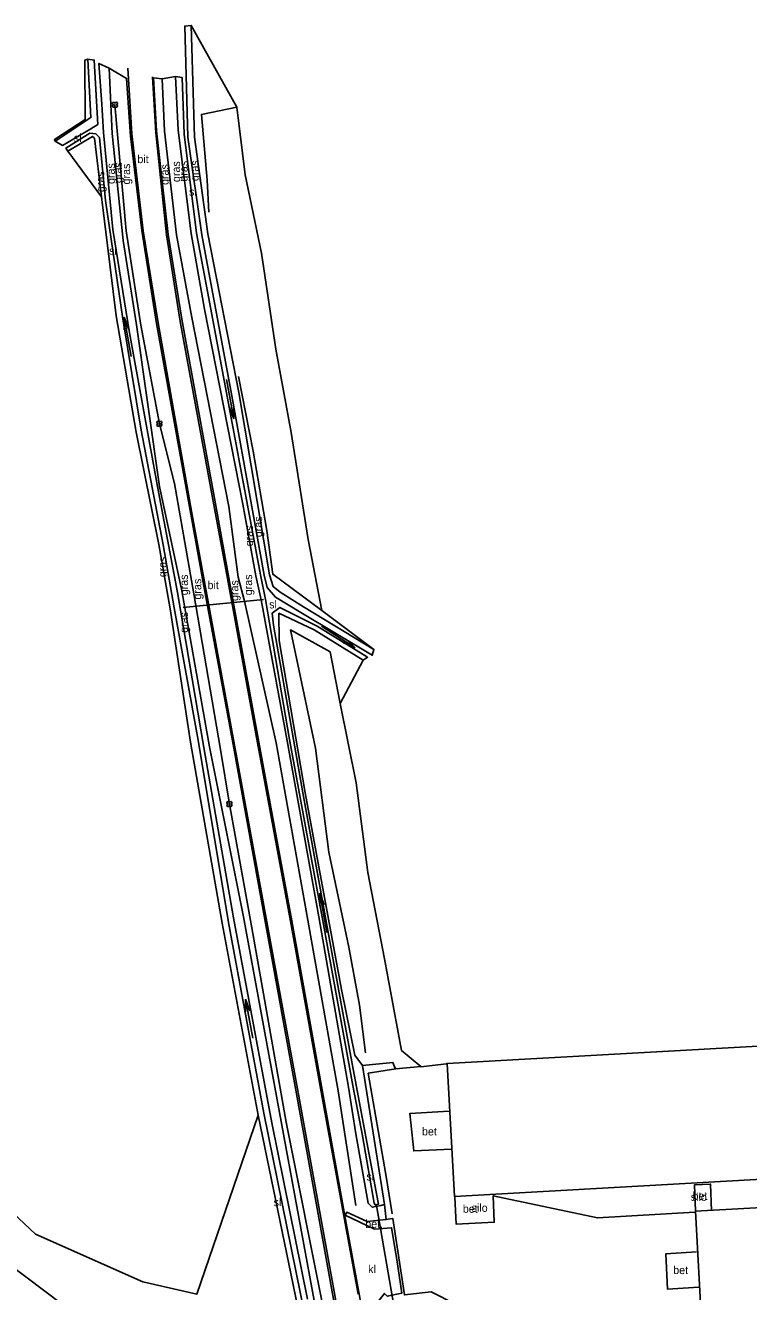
# Model space of a CAD drawing. Extents: x 154825 to 158680, y 370717 to 378075.
# Drawn here: x 155424.8 to 155515.3, y 377327.8 to 377486.1 of the extents above; entities that cross this region are included whole.
import ezdxf

# ---------------------------------------------------------------- set-up
doc = ezdxf.new("R2010")
doc.units = 0
for name, color, linetype in [('beton', 7, 'Continuous'), ('bitumenverharding(vs)', 7, 'Continuous'), ('boom', 7, 'Continuous'), ('breuklijn', 7, 'Continuous'), ('cultuurscheiding', 7, 'Continuous'), ('deelstreep(1-3)', 7, 'Continuous'), ('duiker lijn', 7, 'Continuous'), ('gebouw algemeen', 7, 'Continuous'), ('grazige vegetatie(vs)', 7, 'Continuous'), ('haag geschoren', 7, 'Continuous'), ('haag geschoren+insteek', 7, 'Continuous'), ('hoogteverschillijn', 7, 'Continuous'), ('insteek sloot', 7, 'Continuous'), ('klinkerverharding(vs)', 7, 'Continuous'), ('maaiveldlijn algemeen - gesloten verharding', 7, 'Continuous'), ('maaiveldlijn algemeen - open verharding', 7, 'Continuous'), ('maaiveldlijn algemeen - verharding algemeen', 7, 'Continuous'), ('raster - hek', 7, 'Continuous'), ('Silo_cel', 7, 'Continuous'), ('Sloot bodem', 7, 'Continuous'), ('sloot(vs)', 7, 'Continuous'), ('stroomrichting  watergangen', 7, 'Continuous'), ('vlak_akkerland', 7, 'Continuous'), ('vlak_Grasland', 7, 'Continuous'), ('vlak_Grazige_vegetatie', 7, 'Continuous')]:
    doc.layers.add(name, color=color, linetype=linetype)

msp = doc.modelspace()

# ---------------------------------------------------------------- linework, layer by layer
at = {"layer": 'boom'}
msp.add_lwpolyline([(155450.36, 377388.74), (155453.14, 377373.27), (155457.45, 377348.99), (155462.1, 377325.61)], dxfattribs=at)
for centre in [(155436.04, 377476.14), (155441.6, 377436.27), (155450.36, 377388.74)]:
    msp.add_circle(centre, 0.006, dxfattribs=at)
for centre, start, end in [((155435.89, 377476.3), 357.075, 272.925), ((155435.89, 377475.98), 87.075, 2.925), ((155436.2, 377476.3), 267.075, 182.925), ((155436.2, 377475.98), 177.075, 92.925), ((155441.45, 377436.43), 357.075, 272.925), ((155441.45, 377436.11), 87.075, 2.925), ((155441.76, 377436.43), 267.075, 182.925), ((155441.76, 377436.11), 177.075, 92.925), ((155450.2, 377388.89), 357.075, 272.925), ((155450.2, 377388.58), 87.075, 2.925), ((155450.52, 377388.89), 267.075, 182.925), ((155450.52, 377388.58), 177.075, 92.925)]:
    msp.add_arc(centre, 0.158, start, end, dxfattribs=at)
at = {"layer": 'breuklijn'}
for points in [[(155441.93, 377479.4), (155442.22, 377472.86), (155443.76, 377459.87), (155445.64, 377449.54), (155450.27, 377425.94), (155451.44, 377417.08), (155452.22, 377414.08), (155456.2, 377396.39), (155460.14, 377374.23), (155463.95, 377352.91), (155466.15, 377338.57)], [(155441.6, 377436.27), (155443.47, 377428.79), (155445.9, 377415.02), (155449.24, 377395.55), (155450.36, 377388.74)]]:
    msp.add_lwpolyline(points, dxfattribs=at)
at = {"layer": 'cultuurscheiding'}
msp.add_lwpolyline([(155470.99, 377355.91), (155471.15, 377355.63)], dxfattribs=at)
at = {"layer": 'deelstreep(1-3)'}
for points in [[(155437.66, 377480.71), (155438.16, 377472.53), (155439.59, 377460.39), (155441.45, 377448.89), (155445.6, 377425.35), (155447.26, 377416.5), (155450.91, 377396.55), (155455.12, 377373.55), (155458.93, 377352.67), (155463.84, 377325.72), (155466.95, 377308.73), (155469.14, 377296.77), (155472.64, 377277.72), (155474.84, 377265.78), (155475.54, 377261.77), (155476.99, 377253.79), (155477.67, 377248.89), (155478.31, 377241.77), (155478.57, 377236.78), (155478.71, 377229.69), (155478.45, 377221.57), (155477.91, 377213.49), (155477.46, 377208.51), (155476.34, 377200.59)], [(155440.75, 377479.62), (155441.17, 377472.64), (155442.51, 377459.88), (155444.19, 377449.04), (155448.51, 377425.69), (155450.11, 377416.95), (155453.67, 377397.53), (155457.97, 377374.09), (155462.05, 377351.58), (155466.44, 377327.46)]]:
    msp.add_lwpolyline(points, dxfattribs=at)
at = {"layer": 'duiker lijn'}
for points in [[(155454.6, 377414.3), (155444.57, 377413.3)], [(155471.29, 377323.9), (155468.74, 377338.58)]]:
    msp.add_lwpolyline(points, dxfattribs=at)
at = {"layer": 'gebouw algemeen'}
for points in [[(155477.56, 377356.3), (155541.13, 377359.87), (155542.07, 377343.27)], [(155477.56, 377356.3), (155478.49, 377339.7), (155542.07, 377343.27)], [(155509.43, 377323.28), (155551.72, 377325.63), (155550.88, 377340.19), (155508.61, 377337.85)], [(155508.61, 377337.85), (155509.43, 377323.28)]]:
    msp.add_lwpolyline(points, dxfattribs=at)
at = {"layer": 'haag geschoren'}
for points in [[(155466.98, 377356.05), (155470.79, 377356.45), (155470.99, 377355.91)], [(155469.73, 377338.7), (155469.93, 377336.83)]]:
    msp.add_lwpolyline(points, dxfattribs=at)
at = {"layer": 'haag geschoren+insteek'}
msp.add_lwpolyline([(155469.73, 377338.7), (155466.98, 377356.05)], dxfattribs=at)
at = {"layer": 'hoogteverschillijn'}
for points in [[(155451.47, 377442.16), (155453.33, 377432.86), (155455.05, 377422.95), (155455.77, 377417.47), (155461.92, 377412.95), (155460.22, 377421.82), (155458.09, 377435.16), (155456.15, 377445.58), (155454.35, 377457.58), (155452.31, 377467.38), (155451.3, 377475.83), (155446.87, 377474.93), (155447.57, 377466.71), (155447.77, 377462.71)], [(155471.85, 377357.93), (155469.73, 377369.39), (155467.64, 377380.18), (155466.19, 377391.38), (155464.22, 377401.31), (155462.93, 377407.78), (155458.01, 377410.51), (155461.13, 377395.73), (155462.78, 377382.72), (155465.28, 377370.84), (155466.6, 377363.59), (155467.35, 377357.66)], [(155417.64, 377342.88), (155426.1, 377334.99), (155439.54, 377329.02), (155446.29, 377327.48)], [(155431.86, 377324.38), (155422.53, 377331.44)]]:
    msp.add_lwpolyline(points, dxfattribs=at)
at = {"layer": 'insteek sloot'}
for points in [[(155468.42, 377408.07), (155459.63, 377413.37), (155456.7, 377415.23), (155455.84, 377415.91), (155455.37, 377417.37), (155451.54, 377440.16), (155447.67, 377460), (155446.01, 377472.1), (155445.59, 377486.07)], [(155432.66, 377481.84), (155433.05, 377474.55), (155428.56, 377471.58)], [(155435.31, 377480.71), (155435.7, 377472.57), (155437.06, 377459.16), (155438.75, 377448.64), (155441.6, 377428.42), (155444.41, 377415.39), (155447.88, 377395.89), (155452.11, 377374.66), (155456.6, 377350.19), (155460.96, 377326.69), (155463.34, 377313.74), (155464.93, 377304.29), (155464.68, 377303.32), (155463.8, 377303.1), (155463.38, 377303.31)], [(155443.62, 377479.66), (155443.95, 377472.96), (155445.59, 377460.04), (155447.26, 377450.59), (155452.03, 377426.21), (155453.64, 377417.26), (155454.33, 377414.28), (155457.58, 377396.65), (155461.52, 377374.64), (155465.23, 377353.37), (155466.16, 377347.52), (155467.68, 377338.84), (155468.2, 377338.35), (155469.29, 377338.58), (155469.73, 377338.7)], [(155430.15, 377470.36), (155433.22, 377472.19), (155433.5, 377471.96), (155434.37, 377464.65), (155436.19, 377449.77), (155438.71, 377435.24), (155441.52, 377421.18), (155442.96, 377413.12), (155445.51, 377396.47), (155449.46, 377373.84), (155453.96, 377349.87), (155459.15, 377324.59), (155463.38, 377303.31)], [(155466.98, 377356.05), (155466.02, 377357.34), (155464.37, 377365.55), (155459.82, 377390.12), (155456.56, 377409.2), (155456.55, 377412.58), (155460.97, 377410.52), (155467.06, 377406.74)]]:
    msp.add_lwpolyline(points, dxfattribs=at)
at = {"layer": 'maaiveldlijn algemeen - gesloten verharding'}
for points in [[(155437.51, 377479.44), (155437.98, 377472.22), (155439.4, 377460.42), (155441.26, 377448.82), (155445.52, 377424.98), (155447.08, 377416.43), (155450.73, 377396.66), (155454.95, 377373.38), (155458.76, 377352.51), (155463.59, 377325.7)], [(155440.87, 377479.51), (155441.25, 377472.89), (155442.7, 377459.94), (155444.41, 377449.33), (155448.69, 377425.79), (155450.3, 377417), (155454.05, 377396.46), (155458.15, 377374.14), (155462.15, 377351.83), (155464.8, 377337.25), (155467.15, 377324.3)], [(155436.04, 377476.14), (155437.44, 377460.38), (155439.3, 377448.6), (155441.6, 377436.27)]]:
    msp.add_lwpolyline(points, dxfattribs=at)
at = {"layer": 'maaiveldlijn algemeen - open verharding'}
msp.add_lwpolyline([(155467.15, 377324.3), (155469.73, 377327.57), (155470.08, 377327.22), (155471.89, 377327.59), (155471.28, 377331.8), (155470.62, 377335.78), (155468.5, 377335.59), (155464.84, 377337.34)], dxfattribs=at)
at = {"layer": 'maaiveldlijn algemeen - verharding algemeen'}
for points in [[(155470.72, 377337.52), (155469.92, 377342.43), (155467.72, 377355.09), (155471.15, 377355.63)], [(155471.15, 377355.63), (155474.27, 377355.93), (155474.29, 377355.89), (155477.51, 377356.26), (155477.56, 377356.3)], [(155477.83, 377350.35), (155472.9, 377350.04), (155473.39, 377345.38), (155478.11, 377345.62)], [(155508.61, 377337.85), (155508.5, 377341.16), (155510.5, 377341.23), (155510.61, 377337.91)], [(155478.52, 377339.6), (155478.69, 377336.23), (155483.47, 377336.47), (155483.33, 377339.77), (155496.36, 377337.01), (155508.53, 377337.71)], [(155464.8, 377337.25), (155465.03, 377337.72), (155467.58, 377336.54), (155469.93, 377336.83)], [(155469.93, 377336.83), (155470.43, 377336.89), (155470.78, 377336.95), (155472.24, 377327.39), (155475.56, 377327.76), (155481.58, 377324.71), (155486.52, 377322.24)], [(155509.05, 377328.35), (155505.13, 377328.1), (155504.92, 377332.53), (155508.75, 377332.78)]]:
    msp.add_lwpolyline(points, dxfattribs=at)
at = {"layer": 'raster - hek'}
msp.add_lwpolyline([(155432.26, 377481.7), (155432.31, 377474.29), (155428.48, 377471.8)], dxfattribs=at)
at = {"layer": 'Sloot bodem'}
for points in [[(155468.2, 377407.34), (155459.27, 377412.67), (155456.12, 377414.6), (155455.06, 377415.79), (155454.7, 377417.36), (155450.64, 377439.77), (155446.89, 377459.87), (155445.16, 377472.08), (155444.78, 377485.97)], [(155429.47, 377471.06), (155433.05, 377473.13), (155433.91, 377473.69), (155433.46, 377481.73)], [(155434.04, 377481.32), (155434.42, 377476.2), (155434.62, 377472.69), (155435.8, 377460.55), (155437.85, 377447.62), (155441.35, 377428.42), (155443.88, 377415.17), (155447.17, 377395.8), (155450.88, 377374.51), (155455.65, 377348.89), (155460.12, 377326.87)], [(155444.43, 377479.54), (155444.68, 377472.47), (155446.22, 377460.09), (155448.02, 377450.6), (155452.6, 377426.09), (155454.24, 377417.39), (155454.85, 377414.29), (155457.86, 377396.79), (155461.94, 377374.6), (155465.78, 377353.55), (155466.98, 377347.26), (155468.44, 377338.87), (155468.59, 377338.64), (155468.99, 377338.72), (155468.91, 377339.16), (155465.73, 377356.04), (155463.99, 377365.61), (155459.54, 377390.16), (155455.85, 377411.08), (155455.71, 377412.6), (155456.64, 377413.31), (155461.31, 377410.98), (155467.63, 377407.09)], [(155459.81, 377324.63), (155454.65, 377350.1), (155450.22, 377373.93), (155446.45, 377396.74), (155443.46, 377413.28), (155442.06, 377421.12), (155439.34, 377435.49), (155437.04, 377449.4), (155434.86, 377464.18), (155434.13, 377472.05), (155433.66, 377472.52), (155432.9, 377472.61), (155429.92, 377470.73)]]:
    msp.add_lwpolyline(points, dxfattribs=at)
at = {"layer": 'stroomrichting  watergangen'}
for p, q in [((155437.18, 377449.59), (155437.19, 377448.01)), ((155438.09, 377444.69), (155437.19, 377449.6)), ((155437.19, 377449.6), (155437.74, 377448.12)), ((155450, 377441.81), (155450.89, 377436.9)), ((155450.89, 377436.9), (155450.34, 377438.38)), ((155450.9, 377436.91), (155450.9, 377438.49)), ((155461.87, 377410.98), (155466.06, 377408.27)), ((155466.05, 377408.29), (155464.9, 377409.37)), ((155466.06, 377408.27), (155464.6, 377408.88)), ((155461.64, 377377.58), (155461.64, 377376)), ((155462.54, 377372.69), (155461.65, 377377.6)), ((155461.65, 377377.6), (155462.19, 377376.12)), ((155452.36, 377364.36), (155452.37, 377362.78)), ((155453.27, 377359.46), (155452.38, 377364.37)), ((155452.38, 377364.37), (155452.92, 377362.89))]:
    msp.add_line(p, q, dxfattribs=at)
at = {"layer": 'vlak_akkerland'}
msp.add_lwpolyline([(155332.6, 377406.06), (155336.93, 377409.48), (155343.4, 377413.36), (155347.88, 377416.5), (155347.67, 377415.7), (155352.79, 377409.99), (155356.85, 377405.55), (155360.64, 377401.81), (155369.42, 377391.91), (155377.47, 377383.61), (155385.94, 377374.1), (155392.86, 377367.05), (155401.97, 377357.18), (155410.79, 377349.42), (155417.64, 377342.88), (155426.1, 377334.99), (155439.54, 377329.02), (155446.29, 377327.48), (155453.96, 377349.87), (155459.15, 377324.59)], dxfattribs=at)
at = {"layer": 'vlak_Grasland'}
for points in [[(155461.92, 377412.95), (155468.42, 377408.07), (155459.63, 377413.37), (155456.7, 377415.23), (155455.84, 377415.91), (155455.37, 377417.37), (155451.54, 377440.16), (155447.67, 377460), (155446.01, 377472.1), (155445.59, 377486.07), (155451.3, 377475.83), (155452.31, 377467.38), (155454.35, 377457.58), (155456.15, 377445.58), (155458.09, 377435.16), (155460.22, 377421.82)], [(155471.85, 377357.93), (155474.27, 377355.93), (155471.15, 377355.63), (155470.99, 377355.91), (155470.79, 377356.45), (155466.98, 377356.05), (155466.02, 377357.34), (155464.37, 377365.55), (155459.82, 377390.12), (155456.56, 377409.2), (155456.55, 377412.58), (155460.97, 377410.52), (155467.06, 377406.74), (155464.22, 377401.31), (155466.19, 377391.38), (155467.64, 377380.18), (155469.73, 377369.39)]]:
    msp.add_lwpolyline(points, close=True, dxfattribs=at)
at = {"layer": 'vlak_Grazige_vegetatie'}
for points in [[(155468.42, 377408.07), (155468.2, 377407.34), (155459.27, 377412.67), (155456.12, 377414.6), (155455.06, 377415.79), (155454.7, 377417.36), (155450.64, 377439.77), (155446.89, 377459.87), (155445.16, 377472.08), (155444.78, 377485.97), (155445.59, 377486.07), (155446.01, 377472.1), (155447.67, 377460), (155451.54, 377440.16), (155455.37, 377417.37), (155455.84, 377415.91), (155456.7, 377415.23), (155459.63, 377413.37)], [(155433.05, 377474.55), (155428.56, 377471.58), (155428.48, 377471.8), (155432.31, 377474.29), (155432.26, 377481.7), (155432.66, 377481.84)], [(155433.05, 377473.13), (155429.47, 377471.06), (155428.56, 377471.58), (155433.05, 377474.55), (155432.66, 377481.84), (155433.46, 377481.73), (155433.91, 377473.69)], [(155443.62, 377479.66), (155443.95, 377472.96), (155445.59, 377460.04), (155447.26, 377450.59), (155452.03, 377426.21), (155453.64, 377417.26), (155454.33, 377414.28), (155457.58, 377396.65), (155461.52, 377374.64), (155465.23, 377353.37), (155466.16, 377347.52), (155467.68, 377338.84), (155468.2, 377338.35), (155469.29, 377338.58), (155469.73, 377338.7), (155469.93, 377336.83), (155467.58, 377336.54), (155465.03, 377337.72), (155464.8, 377337.25), (155462.15, 377351.83), (155458.15, 377374.14), (155454.05, 377396.46), (155450.3, 377417), (155448.69, 377425.79), (155444.41, 377449.33), (155442.7, 377459.94), (155441.25, 377472.89), (155440.87, 377479.51), (155441.93, 377479.4)], [(155468.44, 377338.87), (155468.59, 377338.64), (155468.99, 377338.72), (155468.91, 377339.16), (155465.73, 377356.04), (155463.99, 377365.61), (155459.54, 377390.16), (155455.85, 377411.08), (155455.71, 377412.6), (155456.64, 377413.31), (155461.31, 377410.98), (155467.63, 377407.09), (155467.06, 377406.74), (155460.97, 377410.52), (155456.55, 377412.58), (155456.56, 377409.2), (155459.82, 377390.12), (155464.37, 377365.55), (155466.02, 377357.34), (155466.98, 377356.05), (155469.73, 377338.7), (155469.29, 377338.58), (155468.2, 377338.35), (155467.68, 377338.84), (155466.16, 377347.52), (155465.23, 377353.37), (155461.52, 377374.64), (155457.58, 377396.65), (155454.33, 377414.28), (155453.64, 377417.26), (155452.03, 377426.21), (155447.26, 377450.59), (155445.59, 377460.04), (155443.95, 377472.96), (155443.62, 377479.66), (155444.43, 377479.54), (155444.68, 377472.47), (155446.22, 377460.09), (155448.02, 377450.6), (155452.6, 377426.09), (155454.24, 377417.39), (155454.85, 377414.29), (155457.86, 377396.79), (155461.94, 377374.6), (155465.78, 377353.55), (155466.98, 377347.26)], [(155433.5, 377471.96), (155434.37, 377464.65), (155430.15, 377470.36), (155433.22, 377472.19)]]:
    msp.add_lwpolyline(points, close=True, dxfattribs=at)
for points in [[(155460.12, 377326.87), (155455.65, 377348.89), (155450.88, 377374.51), (155447.17, 377395.8), (155443.88, 377415.17), (155441.35, 377428.42), (155437.85, 377447.62), (155435.8, 377460.55), (155434.62, 377472.69), (155434.42, 377476.2), (155434.04, 377481.32), (155435.31, 377480.71), (155435.7, 377472.57), (155437.06, 377459.16), (155438.75, 377448.64), (155441.6, 377428.42), (155444.41, 377415.39), (155447.88, 377395.89), (155452.11, 377374.66), (155456.6, 377350.19), (155460.96, 377326.69)], [(155460.96, 377326.69), (155456.6, 377350.19), (155452.11, 377374.66), (155447.88, 377395.89), (155444.41, 377415.39), (155441.6, 377428.42), (155438.75, 377448.64), (155437.06, 377459.16), (155435.7, 377472.57), (155435.31, 377480.71), (155437.51, 377479.44), (155437.98, 377472.22), (155439.4, 377460.42), (155441.26, 377448.82), (155445.52, 377424.98), (155447.08, 377416.43), (155450.73, 377396.66), (155454.95, 377373.38), (155458.76, 377352.51), (155463.59, 377325.7)], [(155459.15, 377324.59), (155453.96, 377349.87), (155449.46, 377373.84), (155445.51, 377396.47), (155442.96, 377413.12), (155441.52, 377421.18), (155438.71, 377435.24), (155436.19, 377449.77), (155434.37, 377464.65), (155433.5, 377471.96), (155433.22, 377472.19), (155430.15, 377470.36), (155429.92, 377470.73), (155432.9, 377472.61), (155433.66, 377472.52), (155434.13, 377472.05), (155434.86, 377464.18), (155437.04, 377449.4), (155439.34, 377435.49), (155442.06, 377421.12), (155443.46, 377413.28), (155446.45, 377396.74), (155450.22, 377373.93), (155454.65, 377350.1), (155459.81, 377324.63)]]:
    msp.add_lwpolyline(points, dxfattribs=at)

# ---------------------------------------------------------------- texts
at = {"layer": 'beton'}
for p in [(155474.43, 377347.32), (155508.24, 377339.26), (155479.53, 377337.65), (155505.83, 377329.99)]:
    msp.add_text('bet', height=1, dxfattribs=at).set_placement(p)
at = {"layer": 'bitumenverharding(vs)'}
for p in [(155438.85, 377468.85), (155447.62, 377415.6)]:
    msp.add_text('bit', height=1, dxfattribs=at).set_placement(p)
at = {"layer": 'grazige vegetatie(vs)'}
for p in [(155434.72, 377465.23), (155436.03, 377466.24), (155436.92, 377466.36), (155437.94, 377466.18), (155442.75, 377466.12), (155444.18, 377466.48), (155445.13, 377466.54), (155446.5, 377466.6), (155453.31, 377420.96), (155454.44, 377422.09), (155442.48, 377417.09), (155445.16, 377414.83), (155453.19, 377414.83), (155446.83, 377414.3), (155451.46, 377414.12), (155445.16, 377410.14)]:
    msp.add_text('gras', height=1, rotation=90, dxfattribs=at).set_placement(p)
at = {"layer": 'klinkerverharding(vs)'}
for s, p in [('bet.', (155467.34, 377335.76)), ('kl', (155467.7, 377330.11))]:
    msp.add_text(s, height=1, dxfattribs=at).set_placement(p)
at = {"layer": 'maaiveldlijn algemeen - verharding algemeen'}
msp.add_text('bet', height=1, dxfattribs=at).set_placement((155479.53, 377337.65))
at = {"layer": 'Silo_cel'}
for p in [(155508.03, 377339.12), (155480.63, 377337.77)]:
    msp.add_text('silo', height=1, dxfattribs=at).set_placement(p)
at = {"layer": 'sloot(vs)'}
for p in [(155430.91, 377471.5), (155445.3, 377464.78), (155435.31, 377457.4), (155455.32, 377413.19), (155467.48, 377341.69), (155455.88, 377338.48)]:
    msp.add_text('sl', height=1, dxfattribs=at).set_placement(p)

doc.saveas('drawing.dxf')
